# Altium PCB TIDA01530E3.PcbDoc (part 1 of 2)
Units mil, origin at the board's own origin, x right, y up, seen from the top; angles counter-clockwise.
Board outline 3700 x 4450 mil, 2 copper layers (Top Layer, Bottom Layer), stack 62 mil thick; 148 components, 116 nets, 531 pads, 208 vias.
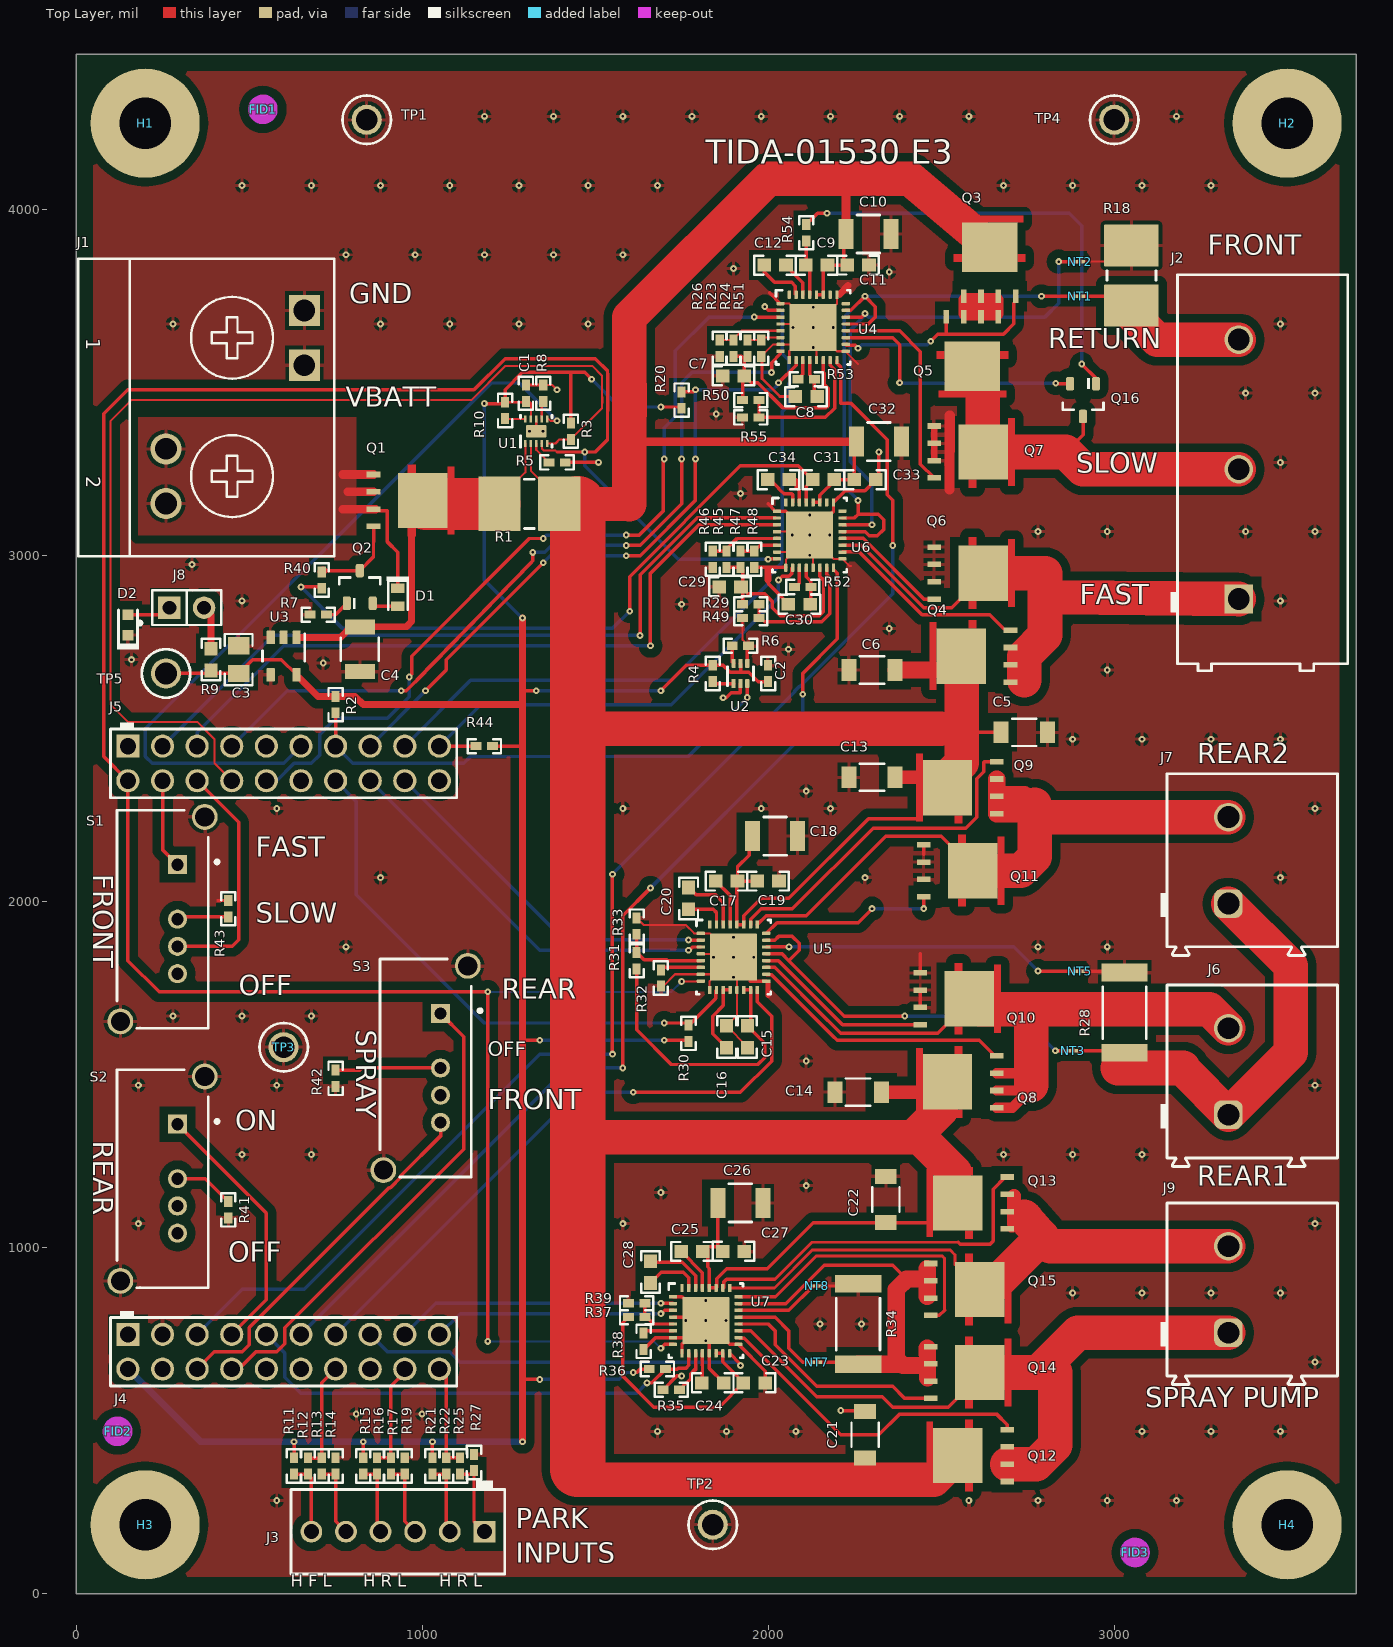
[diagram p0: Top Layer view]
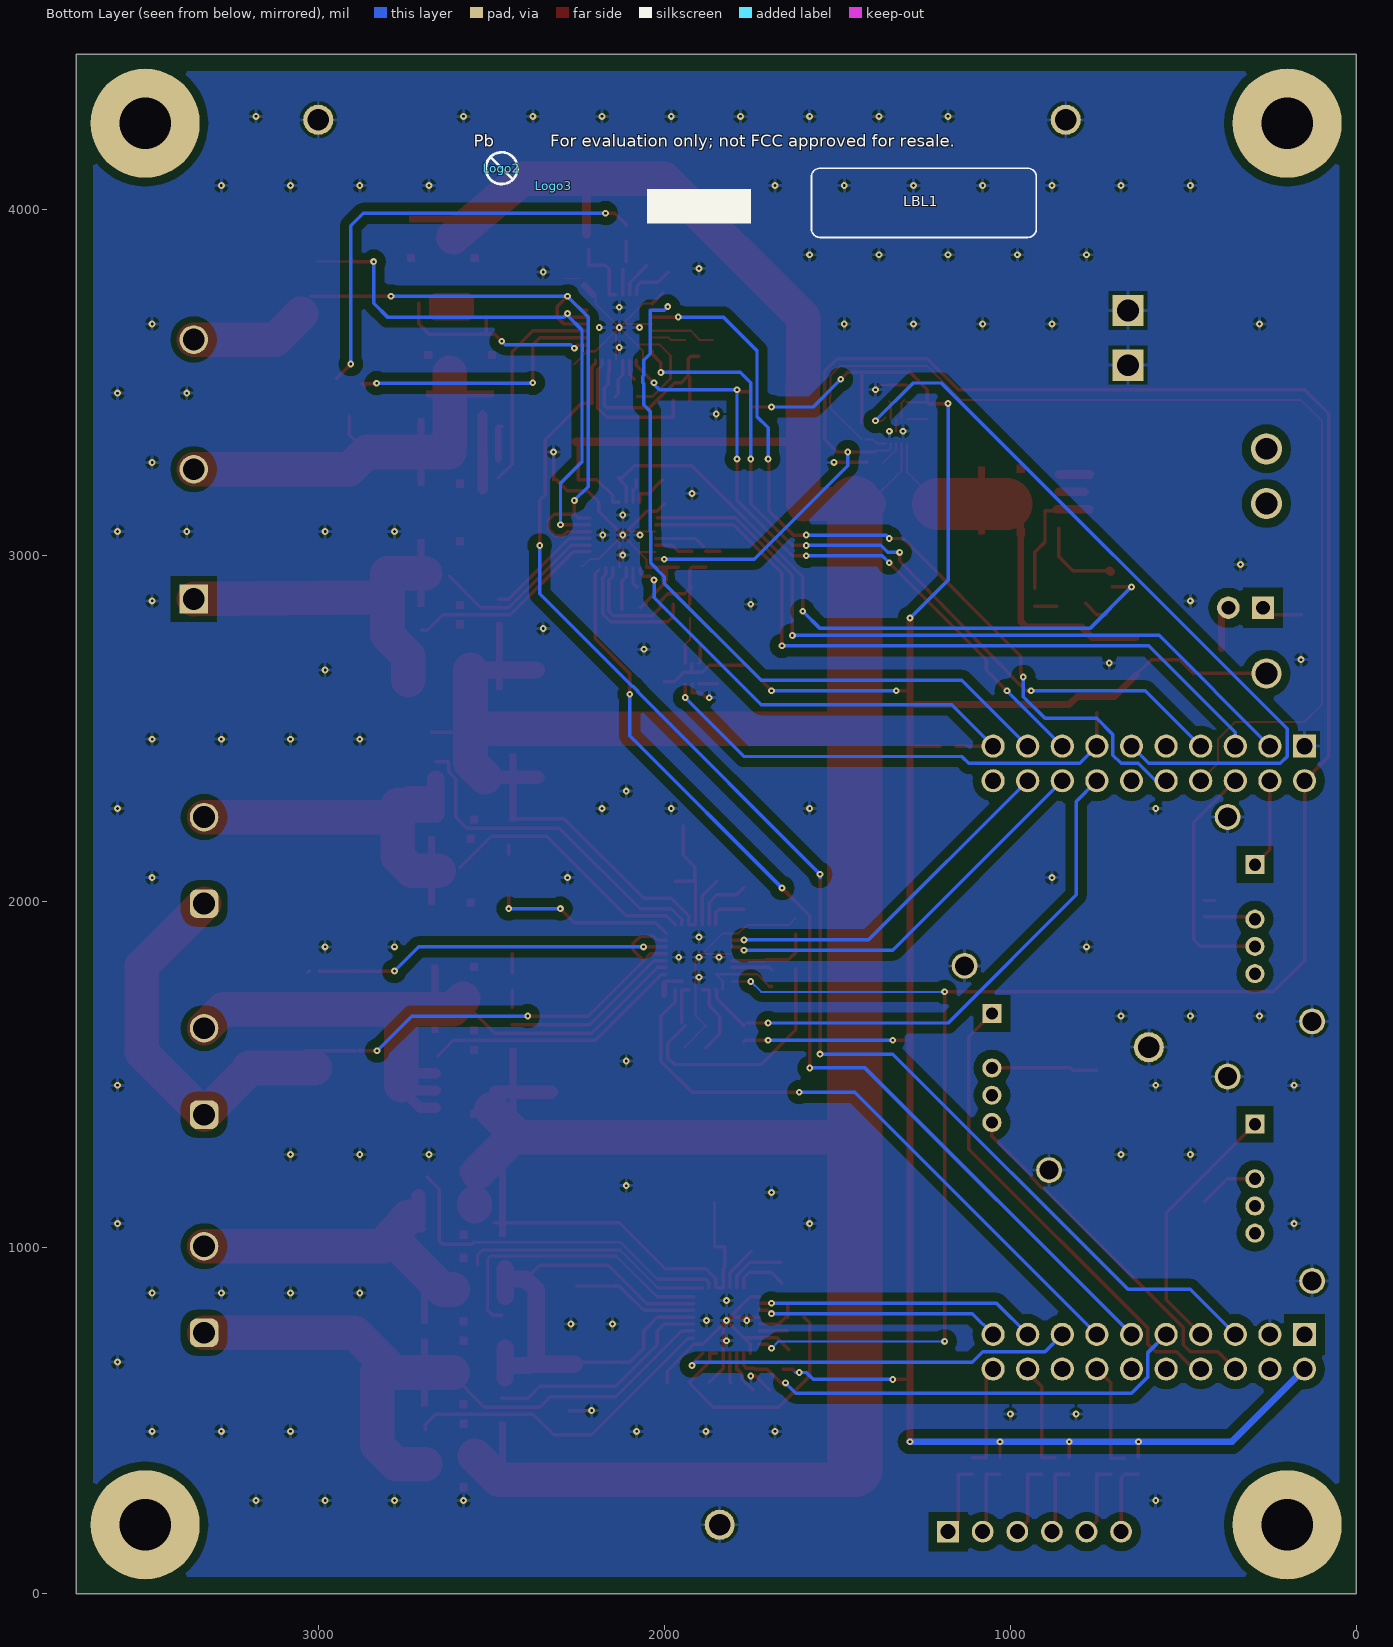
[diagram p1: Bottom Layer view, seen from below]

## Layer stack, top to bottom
Top Solder: solder mask 0.4, Solder Resist, Dk 3.5
Top Layer: signal copper 2.8
Dielectric1: core 56.4, FR-4, Dk 4.8
Bottom Layer: signal copper 2.8
Bottom Solder: solder mask 0.4, Solder Resist, Dk 3.5

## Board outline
0,0 0,4450 3700,4450 3700,0

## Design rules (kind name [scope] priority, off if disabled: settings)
AcuteAngle [All] p1: minimum=4.50000000000000E+0001 checktracksonly=FALSE
AssemblyTestPointUsage [All] p1: valid=2
BoardOutlineClearance BoardOutlineClearance_MountingHoles [OnCopper and InComponentClass('Mounting Holes')] p1: gap=40 ignorepadtopadclearanceinfootprint=FALSE
BoardOutlineClearance BoardOutlineClearance_Poly [OnCopper and IsPoly] p2: gap=25 ignorepadtopadclearanceinfootprint=FALSE
BoardOutlineClearance [OnCopper and Not InComponentClass('Logo') and not InComponentClass('FiducialMark') and not InRegion(1000,500,4000,800) and not InPoly] p3: gap=75 ignorepadtopadclearanceinfootprint=FALSE
Clearance Clearance_Keepouts [((IsTrack Or IsArc) And Not InPoly) And IsFree and IsKeepOut vs ((IsTrack Or IsArc) And Not InPoly) And IsFree and IsKeepOut] p1: gap=0 ignorepadtopadclearanceinfootprint=FALSE
Clearance Clearance_Poly [InPolygon] p2: gap=25 ignorepadtopadclearanceinfootprint=FALSE except(0: Arc-Hole Track-Hole SMDPad-Hole THPad-Hole Via-Hole Fill-Hole Poly-Hole Region-Hole Text-Hole)
Clearance [All] p3: gap=7.87 ignorepadtopadclearanceinfootprint=FALSE except(0: Arc-Hole Track-Hole SMDPad-Hole THPad-Hole Via-Hole Fill-Hole Poly-Hole Region-Hole Text-Hole)
ComponentClearance ComponentClearance_MountingHoles_FiducialMarks [InComponentClass('Mounting Holes') vs InComponentClass('FiducialMark')] p1: gap=50 collisioncheckmode=3 verticalgap=10 showdistances=FALSE
ComponentClearance ComponentClearance_Shunt [InComponentClass('Header') vs InComponentClass('Shunt')] p2: gap=0 collisioncheckmode=3 verticalgap=0 showdistances=FALSE
ComponentClearance ComponentClearance_Logo [InComponentClass('Logo')] p3: gap=50 collisioncheckmode=3 verticalgap=10 showdistances=FALSE
ComponentClearance ComponentClearance_ScrewToNut [(HasFootprint('NY PMS 440 0025 PH')) vs (HasFootprint('Keystone_1902C'))] p4: gap=5 collisioncheckmode=3 verticalgap=10 showdistances=FALSE
ComponentClearance ComponentClearance_MountingHoles [InComponentClass('Mounting Holes')] p5: gap=250 collisioncheckmode=3 verticalgap=100000 showdistances=FALSE
ComponentClearance ComponentClearance_SmallPassives [HasFootprint('0201*') or HasFootprint('0402*') or HasFootprint('0508') or HasFootprint('0603*') or HasFootprint('0612') or HasFootprint('0805*') or HasFootprint('0815*') or HasFootprint('0830*') or HasFootprint('1206*') or HasFootprint('1210*') or HasFootprint('1808*') or HasFootprint('1812*') or HasFootprint('1825*') or HasFootprint('2010*') or HasFootprint('2220*') or HasFootprint('2225*') or HasFootprint('2512*') or HasFootprint('2728*') or HasFootprint('3518*') vs HasFootprint('0201*') or HasFootprint('0402*') or HasFootprint('0508') or HasFootprint('0603*') or HasFootprint('0612') or HasFootprint('0805*') or HasFootprint('0815*') or HasFootprint('0830*') or HasFootprint('1206*') or HasFootprint('1210*') or HasFootprint('1808*') or HasFootprint('1812*') or HasFootprint('1825*') or HasFootprint('2010*') or HasFootprint('2220*') or HasFootprint('2225*') or HasFootprint('2512*') or HasFootprint('2728*') or HasFootprint('3518*')] p6: gap=14.96 collisioncheckmode=3 verticalgap=10 showdistances=FALSE
ComponentClearance ComponentClearance_THtoSMT [IsThruComponent vs IsSMTComponent] p7: gap=40 collisioncheckmode=3 verticalgap=30 showdistances=FALSE
ComponentClearance ComponentClearance_THtoTH [IsThruComponent vs IsThruComponent] p8: gap=30 collisioncheckmode=3 verticalgap=30 showdistances=FALSE
ComponentClearance [All] p9: gap=30 collisioncheckmode=3 verticalgap=10 showdistances=FALSE
DiffPairsRouting [All] p1: maxlimit=100 minlimit=10 mostfreqgap=10 toplayer_minwidth=15 toplayer_maxwidth=15 toplayer_prefwidth=15 bottomlayer_minwidth=15 bottomlayer_maxwidth=15 bottomlayer_prefwidth=15 maxuncoupledlength=1000
FabricationTestPointUsage TestPointUsage [All] p1: valid=2 allowmultiple=FALSE
FabricationTestpoint Testpoint [All] p1: side=3 testpointundercomponent=TRUE minsize=40 maxsize=100 preferedsize=60 minholesize=0 maxholesize=40 preferedholesize=32 testpointgrid=1 allowsidetop=TRUE allowsidebottom=TRUE usegrid=TRUE gridtolerance=0.01
FanoutControl Fanout_LCC [IsLCC] p1: bgadir=Out bgaviamode=Centered fanoutstyle=Auto fanoutdirection=Alternating viagrid=1 // Fanout_LCC (Default Rule)
FanoutControl Fanout_BGA [IsBGA] p2: bgadir=Out bgaviamode=Centered fanoutstyle=Auto fanoutdirection=Alternating viagrid=1 // Fanout_BGA (Default Rule)
FanoutControl Fanout_Default [All] p4: bgadir=Out bgaviamode=Centered fanoutstyle=Auto fanoutdirection=Alternating viagrid=1 // Fanout_Default (Default Rule)
FanoutControl Fanout_Small [(CompPinCount < 5)] p5: bgadir=Out bgaviamode=Centered fanoutstyle=Auto fanoutdirection=OutThenIn viagrid=1 // Fanout_Small (Default Rule)
HoleSize [All] p1: absolutevalues=TRUE maxlimit=251 minlimit=7.87 maxpercent=80.000 minpercent=20.000
MinimumAnnularRing MinimumAnnularRing_ThermalPadVias [IsVia and InAnyComponent] p1: minimumring=5.91
MinimumAnnularRing [All] p2: minimumring=5.9
MinimumSolderMaskSliver MinimumSolderMaskSliver_Logo [InComponentClass('Logo') vs InComponentClass('Logo')] p1: minsoldermaskwidth=0.7
MinimumSolderMaskSliver [All] p2: minsoldermaskwidth=3.94
PlaneConnect [All] p1: planeconnectstyle=Relief reliefexpansion=10 reliefentries=4 reliefconductorwidth=10 reliefairgap=10
PolygonConnect [All] p1: connectstyle=Relief reliefconductorwidth=10 reliefentries=4 polygonreliefangle="90 Angle" airgapwidth=10
RoutingVias ThermalPadVias [IsVia and InAnyComponent] p1: holewidth=7.87 width=19.68 viastyle="Through Hole" minholewidth=7.87 minwidth=19.68 maxholewidth=12.99 maxwidth=23.62
RoutingVias [All] p2: holewidth=16 width=34 viastyle="Through Hole" minholewidth=7 minwidth=19 maxholewidth=40 maxwidth=65
SilkToBoardRegionClearance [Not ((IsComment or IsDesignator) And (Hide <> 'False')) and not InRegion(1000,500,4000,800)] p1:
SilkToSilkClearance SilkToSilkClearance_Pb-FreeLogo [(HasFootprint('Pb-Free_Overlay_Medium') OR HasFootprint('Pb-Free_Overlay_Small')) vs (HasFootprint('Pb-Free_Overlay_Medium') OR HasFootprint('Pb-Free_Overlay_Small'))] p1: silktosilkclearance=0
SilkToSilkClearance [All] p2: silktosilkclearance=4
SilkToSolderMaskClearance SilkToComponentPadClearance [(IsPad or IsFill or IsRegion) and InAnycomponent] p1: minsilkscreentomaskgap=4 clearancetoexposedcopper=TRUE
SilkToSolderMaskClearance "Silk to Solder Mask Opening" [All] p2: minsilkscreentomaskgap=4 clearancetoexposedcopper=FALSE
SolderMaskExpansion [All] p1: expansion=1.97
Width [All] p1: maxlimit=160 minlimit=6 preferedwidth=10 minimp=50.000000 maximp=50.000000 favimp=50.000000 checkconnectedcopper=TRUE
15 further rules are at their usual default settings.

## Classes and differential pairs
component class "TIDA01530 Front Wipers 2x 8702D v2": C1 C2 C3 C4 C5 C6 C7 C8 C9 C10 C11 C12 C29 C30 C31 C32 C33 C34 D1 D2 D? J1 J2 J4 J5 J8 NT1 NT2 Q1 Q2 Q3 Q4 Q5 Q6 Q7 Q16 R1 R2 R3 R4 R5 R6 R7 R8 R9 R10 R18 R20 R23 R24 R26 R29 R40 R44 R45 R46 R47 R48 R49 R50 R51 R52 R53 R54 R55 U1 U2 U3 U4 U6
component class "TIDA01530 Rear Wipers": C13 C14 C15 C16 C17 C18 C19 C20 C21 C22 C23 C24 C25 C26 C27 C28 C? J6 J7 J9 NT3 NT5 NT7 NT8 NT? Q8 Q9 Q10 Q11 Q12 Q13 Q14 Q15 Q? R28 R30 R31 R32 R33 R34 R35 R36 R37 R38 R39 R? U5 U7 U?
component class "Mounting Holes": H1 H2 H3 H4
component class "TIDA01530 Switches Connectors": FID1 FID2 FID3 H1 H2 H3 H4 J3 LBL1 Logo2 Logo3 R11 R12 R13 R14 R15 R16 R17 R19 R21 R22 R25 R27 R41 R42 R43 S1 S2 S3 S? TP1 TP2 TP3 TP4 TP5 TP? ZZ1
component class FiducialMark: FID1 FID2 FID3
component class AssemblyNote: ZZ1
component class Label: LBL1
component class Header: J8

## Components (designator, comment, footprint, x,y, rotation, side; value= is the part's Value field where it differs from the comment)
C1 "C0402C104K4RACAUTO" 0402 1300,3470 r90 top value=0.1uF
C2 "C0402C104K4RACAUTO" 0402 2000,2660 r90 top value=0.1uF
C3 "C2012X7R1A475M125AC" 0805_HV 470,2700 r90 top value=4.7uF
C4 "UMK325AB7106KMHT" 1210_280 820,2730 r270 top value=10uF
C5 "CL31B106KBHNNNE" 1206_180 2740,2490 r0 top value=10uF
C6 "CL31B106KBHNNNE" 1206_180 2300,2670 r180 top value=10uF
C7 "GRM188R70J105KA01D" 0603 1900,3520 r180 top value=1uF
C8 "GRM188R70J105KA01D" 0603 2110,3460 r180 top value=1uF
C9 "C1608X7R1C105K080AC" 0603 2140,3840 r180 top value=1uF
C10 "C3225X7S1H106K250AB" 1210_280 2290,3930 r0 top value=10uF
C11 "C1608X7R1H104K080AA" 0603 2260,3840 r0 top value=0.1uF
C12 "C1608X7R1H104K080AA" 0603 2020,3840 r180 top value=0.1uF
C13 "CL31B106KBHNNNE" 1206_180 2300,2360 r180 top value=10uF
C14 "CL31B106KBHNNNE" 1206_180 2260,1450 r180 top value=10uF
C15 "GRM188R70J105KA01D" 0603 1940,1610 r270 top value=1uF
C16 "GRM188R70J105KA01D" 0603 1880,1610 r90 top value=1uF
C17 "C1608X7R1C105K080AC" 0603 1880,2060 r180 top value=1uF
C18 "C3225X7S1H106K250AB" 1210_280 2020,2190 r0 top value=10uF
C19 "C1608X7R1H104K080AA" 0603 2000,2060 r0 top value=0.1uF
C20 "C1608X7R1H104K080AA" 0603 1770,2010 r270 top value=0.1uF
C21 "CL31B106KBHNNNE" 1206_180 2280,460 r90 top value=10uF
C22 "CL31B106KBHNNNE" 1206_180 2340,1140 r90 top value=10uF
C23 "GRM188R70J105KA01D" 0603 1960,610 r0 top value=1uF
C24 "GRM188R70J105KA01D" 0603 1840,610 r0 top value=1uF
C25 "C1608X7R1C105K080AC" 0603 1780,990 r180 top value=1uF
C26 "C3225X7S1H106K250AB" 1210_280 1920,1130 r0 top value=10uF
C27 "C1608X7R1H104K080AA" 0603 1900,990 r0 top value=0.1uF
C28 "C1608X7R1H104K080AA" 0603 1660,930 r270 top value=0.1uF
C29 "GRM188R70J105KA01D" 0603 1890,2910 r180 top value=1uF
C30 "GRM188R70J105KA01D" 0603 2090,2860 r180 top value=1uF
C31 "C1608X7R1C105K080AC" 0603 2160,3220 r180 top value=1uF
C32 "C3225X7S1H106K250AB" 1210_280 2320,3330 r0 top value=10uF
C33 "C1608X7R1H104K080AA" 0603 2280,3220 r0 top value=0.1uF
C34 "C1608X7R1H104K080AA" 0603 2030,3220 r180 top value=0.1uF
D1 "CD0603-S0180" Diode_0603 930,2880 r270 top value=90V
D2 "LTST-C191KFKT" LTST-C191_Orange 150,2800 r270 top value=Orange
FID1 "Fiducial" Fiducial10-20 540,4290 r0 top
FID2 "Fiducial" Fiducial10-20 120,470 r0 top
FID3 "Fiducial" Fiducial10-20 3060,120 r0 top
H1 "NY PMS 440 0025 PH" "NY PMS 440 0025 PH" 200,4250 r0 top locked
H2 "NY PMS 440 0025 PH" "NY PMS 440 0025 PH" 3500,4250 r0 top
H3 "NY PMS 440 0025 PH" "NY PMS 440 0025 PH" 200,200 r0 top locked
H4 "NY PMS 440 0025 PH" "NY PMS 440 0025 PH" 3500,200 r0 top
J1 "0399100102" CONN_399100102 460,3430 r270 top
J2 "OSTT7032150" On-Shore_OSTT7032150 3360,3250 r90 top
J3 "1725698" Phoenix_1725698 930,180 r180 top
J4 "CRD-081413-A-G" Major_CRD-081413-A-x 600,700 r90 top
J5 "CRD-081413-A-G" Major_CRD-081413-A-x 600,2400 r90 top
J6 "OSTT7020150" On-Shore_OSTT7020150 3330,1510 r90 top
J7 "OSTT7020150" On-Shore_OSTT7020150 3330,2120 r90 top
J8 "90120-0122" CONN_90120-0122 320,2850 r0 top
J9 "OSTT7020150" On-Shore_OSTT7020150 3330,880 r90 top
LBL1 "Size: 0.65\" x 0.20 \"" Label_650x200 1250,4020 r180 bottom
Logo2 "Pb-Free Symbol" Pb-Free_Overlay_Small 2470,4120 r180 bottom
Logo3 "FCC disclaimer" FCC_disclaimer 2320,4070 r180 bottom
NT1 "Net-Tie" Net-Tie_10mil 2900,3750 r0 top net-tie
NT2 "Net-Tie" Net-Tie_10mil 2900,3850 r0 top net-tie
NT3 "Net-Tie" Net-Tie_10mil 2880,1570 r0 top net-tie
NT5 "Net-Tie" Net-Tie_10mil 2900,1800 r0 top net-tie
NT7 "Net-Tie" Net-Tie_10mil 2140,670 r0 top net-tie
NT8 "Net-Tie" Net-Tie_10mil 2140,890 r0 top net-tie
Q1 "SQJA04EP-T1_GE3" PowerPAK_SO-8L 970,3160 r0 top value=60V
Q2 "MMBTA05LT1G" SOT-23 820,2910 r90 top value="60 V"
Q3 "SQJA06EP-T1_GE3" PowerPAK_SO-8L 2640,3860 r90 top value=60V
Q4 "SQJA06EP-T1_GE3" PowerPAK_SO-8L 2590,2710 r180 top value=60V
Q5 "SQJA06EP-T1_GE3" PowerPAK_SO-8L 2590,3580 r270 top value=60V
Q6 "SQJA06EP-T1_GE3" PowerPAK_SO-8L 2590,2950 r0 top value=60V
Q7 "SQJA06EP-T1_GE3" PowerPAK_SO-8L 2590,3300 r0 top value=60V
Q8 "SQJA06EP-T1_GE3" PowerPAK_SO-8L 2550,1480 r180 top value=60V
Q9 "SQJA06EP-T1_GE3" PowerPAK_SO-8L 2550,2330 r180 top value=60V
Q10 "SQJA06EP-T1_GE3" PowerPAK_SO-8L 2550,1720 r0 top value=60V
Q11 "SQJA06EP-T1_GE3" PowerPAK_SO-8L 2560,2090 r0 top value=60V
Q12 "SQJA06EP-T1_GE3" PowerPAK_SO-8L 2580,400 r180 top value=60V
Q13 "SQJA06EP-T1_GE3" PowerPAK_SO-8L 2580,1130 r180 top value=60V
Q14 "SQJA06EP-T1_GE3" PowerPAK_SO-8L 2580,640 r0 top value=60V
Q15 "SQJA06EP-T1_GE3" PowerPAK_SO-8L 2580,880 r0 top value=60V
Q16 "DMN62D0U-7" SOT-23 2910,3450 r270 top value=60V
R1 "CRE2512-FZ-R001E-3" CRE2512-R1_R4 1310,3150 r0 top value=0.001
R2 "CRCW040210K0JNED" 0402 750,2570 r90 top value=10k
R3 "CRCW040210K0JNED" 0402 1430,3360 r90 top value=10k
R4 "ERJ-2GE0R00X" 0402 1840,2660 r270 top value=0
R5 "CRCW04022K55FKED" 0402 1390,3270 r0 top value=2.55k
R6 "ERJ-2GE0R00X" 0402 1920,2740 r180 top value=0
R7 "CRCW040243K0JNED" 0402 700,2830 r0 top value=43k
R8 "ERJ-2GE0R00X" 0402 1350,3470 r90 top value=0
R9 "CRCW0603200RJNEA" 0603 390,2700 r90 top value=200
R10 "ERJ-2GE0R00X" 0402 1240,3420 r270 top value=0
R11 "CRCW0402100KJNED" 0402 630,370 r270 top value=100k
R12 "ERJ-2GE0R00X" 0402 670,370 r90 top value=0
R13 "ERJ-2GE0R00X" 0402 710,370 r90 top value=0
R14 "ERJ-2GE0R00X" 0402 750,370 r270 top value=0
R15 "CRCW0402100KJNED" 0402 830,370 r270 top value=100k
R16 "ERJ-2GE0R00X" 0402 870,370 r90 top value=0
R17 "ERJ-2GE0R00X" 0402 910,370 r90 top value=0
R18 "CRE2512-FZ-R003E-3" CRE2512-R1_R4 3050,3810 r270 top value=0.003
R19 "ERJ-2GE0R00X" 0402 950,370 r270 top value=0
R20 "CRCW040210K0JNED" 0402 1750,3450 r90 top value=10k
R21 "CRCW0402100KJNED" 0402 1030,370 r270 top value=100k
R22 "ERJ-2GE0R00X" 0402 1070,370 r90 top value=0
R23 "CRCW040268K0JNED" 0402 1900,3600 r270 top value=68k
R24 "CRCW0402200KJNED" 0402 1940,3600 r90 top value=200k
R25 "ERJ-2GE0R00X" 0402 1110,370 r90 top value=0
R26 "CRCW0402200KJNED" 0402 1860,3600 r270 top value=200k
R27 "ERJ-2GE0R00X" 0402 1150,380 r270 top value=0
R28 "MCS3264R005FER" 2512 3030,1680 r270 top value=0.005
R29 "CRCW040268K0JNED" 0402 1950,2860 r0 top value=68k
R30 "CRCW040210K0JNED" 0402 1770,1620 r90 top value=10k
R31 "CRCW040268K0JNED" 0402 1620,1830 r90 top value=68k
R32 "CRCW0402200KJNED" 0402 1690,1780 r270 top value=200k
R33 "CRCW0402200KJNED" 0402 1620,1930 r90 top value=200k
R34 "MCS3264R005FER" 2512 2260,780 r270 top value=0.005
R35 "ERJ-2GE0R00X" 0402 1720,590 r0 top value=0
R36 "CRCW040210K0JNED" 0402 1680,650 r0 top value=10k
R37 "CRCW040268K0JNED" 0402 1620,800 r180 top value=68k
R38 "CRCW0402200KJNED" 0402 1640,730 r270 top value=200k
R39 "CRCW0402200KJNED" 0402 1620,840 r180 top value=200k
R40 "CRCW040210K0JNED" 0402 710,2930 r270 top value=10k
R41 "ERJ-2GE0R00X" 0402 440,1110 r90 top value=0
R42 "ERJ-2GE0R00X" 0402 750,1490 r90 top value=0
R43 "ERJ-2GE0R00X" 0402 440,1980 r270 top value=0
R44 "CRCW040210K0JNED" 0402 1180,2450 r180 top value=10k
R45 "CRCW040268K0JNED" 0402 1880,2990 r270 top value=68k
R46 "CRCW0402200KJNED" 0402 1840,2990 r270 top value=200k
R47 "CRCW0402200KJNED" 0402 1920,2990 r90 top value=200k
R48 "CRCW0402200KJNED" 0402 1960,2990 r90 top value=200k
R49 "CRCW040211K0JNED" 0402 1950,2820 r180 top value=11k
R50 "CRCW040268K0JNED" 0402 1950,3450 r0 top value=68k
R51 "CRCW0402200KJNED" 0402 1980,3600 r90 top value=200k
R52 "ERJ-2GE0R00X" 0402 2100,2910 r180 top value=0
R53 "ERJ-2GE0R00X" 0402 2110,3510 r180 top value=0
R54 "CRCW040210K0JNED" 0402 2110,3933.62 r270 top value=10k
R55 "CRCW040211K0JNED" 0402 1950,3400 r180 top value=11k
S1 "1825255-7" SW_1825255-8 250,1950 r270 top
S2 "1825255-7" SW_1825255-8 250,1200 r270 top
S3 "1825255-7" SW_1825255-8 1010,1520 r270 top
TP1 "5011" Keystone5011 840,4260 r90 top
TP2 "5011" Keystone5011 1840,200 r90 top
TP3 "5011" Keystone5011 600,1580 r90 top
TP4 "5011" Keystone5011 3000,4260 r90 top
TP5 "5008" Keystone5008 260,2660 r90 top
U1 "INA300AIDSQR" DSQ0010A 1330,3360 r90 top
U2 "TMP302DQDRLRQ1" DRL0006A 1920,2660 r90 top
U3 "TPS7B6933QDBVRQ1" DBV0005A_N 600,2710 r270 top
U4 "DRV8702DQRHBRQ1" RHB0032E 2130,3660 r0 top
U5 "DRV8702QRHBRQ1" RHB0032E 1900,1840 r0 top
U6 "DRV8702DQRHBRQ1" RHB0032E 2120,3060 r0 top
U7 "DRV8702QRHBRQ1" RHB0032E 1820,790 r0 top
ZZ1 "This Assembly Note is for PCB labels only" AssemblyNoteLabel 660,4790 r0 top

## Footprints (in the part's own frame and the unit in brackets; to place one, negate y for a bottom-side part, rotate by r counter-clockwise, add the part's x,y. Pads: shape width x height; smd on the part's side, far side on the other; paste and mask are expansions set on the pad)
0402 [mm] "0402 from SM-752 data"
  rect 0.8x0.6 smd: 1(-0.6,0) 2(0.6,0)
  silkscreen extent -1.22,-0.52 1.22,0.52, body extent -0.55,-0.3 0.55,0.3, height 0.6
0603 [mm] "0603 from SM-752 data"
  rect 1x0.95 smd: 1(-0.8,0) 2(0.8,0)
  silkscreen extent -1.52,-0.69 1.52,0.69, body extent -0.87,-0.47 0.87,0.47, height 1
0805_HV [mil] "0805 with 30mil clearance between pads"
  rect 50x63 smd: 1(-40,0) 2(40,0)
  silkscreen extent -74,-40 74,40, body extent -43,-29 43,29, height 57
1206_180 [mm] "1206_180"
  rect 1.1x1.6 smd: 1(-1.7,0) 2(1.7,0)
  silkscreen extent -0.9,-1 0.9,1, body extent -1.75,-0.95 1.75,0.95, height 1.8
1210_280 [mm] "SMD, 2-Leads, Body 3.6x2.8mm, Height 2.8mm"
  rect 1.1x2.2 smd: 1(-1.65,0) 2(1.65,0)
  silkscreen extent -0.84,-1.4 0.84,1.4, body extent -1.8,-1.4 1.8,1.4, height 2.8
2512 [mm] "Chip Resistor, Body 6.3x3.2mm, IPC Medium Density"
  rect 1.3x3.4 smd: 1(-2.95,0) 2(2.95,0)
  silkscreen extent -1.9,-1.6 1.9,1.6, body extent -3.22,-1.67 3.22,1.67, height 0.71
AssemblyNoteLabel [mil] "Assembly Note for PCB Labels"
CONN_90120-0122 [mm] "Molex"
  rect 1.65x1.65 hole 1.016 mask+0: 1(-1.27,0)
  round 1.65 hole 1.016 mask+0: 2(1.27,0)
  silkscreen extent -3.56,-1.27 2.54,1.27, body extent -2.54,-1.27 2.54,1.27, height 9.29
CONN_399100102 [mm] "Molex"
  rect 2.3x2.3 hole 1.587: 1(-7.085,5.08) 1A(-3.075,5.08)
  round 2.3 hole 1.587: 2(3.075,-5.08) 2A(7.085,-5.08)
  silkscreen extent -10.88,-11.53 10.96,7.27, body extent -10.88,-11.53 10.96,7.27, height 31.1
CRE2512-R1_R4 [mm] "SMD, 2-Leads, Body 6.45x3.35mm"
  rrect3% 3.1x4 smd: 1(-2.2,0) 2(2.2,0)
  silkscreen extent -0.35,-1.8 0.35,1.8, body extent -3.32,-1.77 3.33,1.78, height 0.9
DBV0005A_N [mm] "SOT23, 5-Leads, Body 2.9x1.6mm, Pitch 0.95mm, Lead Span 2.8mm, IPC Medium Density"
  rrect17% 1x0.6 smd: 1(-1.375,0.95) 2(-1.375,0) 3(-1.375,-0.95) 4(1.375,-0.95) 5(1.375,0.95)
  silkscreen extent -1.62,-1.55 0.38,1.55, body extent -1.42,-1.46 1.42,1.46, height 1.09
Diode_0603 [mm] "Based on Bourns recommended land pattern Rev 10/09"
  rect 0.7x1 smd: 1(-0.65,0) 2(0.65,0)
  silkscreen extent -1.5,-0.8 0.9,0.8, body extent -0.9,-0.5 0.9,0.5, height 0.85
DRL0006A [mm] "SOTFL, 6-Flat Leads, Body 1.2x1.6x0.6mm, Pitch 0.5mm, TI recommended"
  rrect33% 0.67x0.3 smd: 1(-0.74,0.5) 2(-0.74,0) 3(-0.74,-0.5) 4(0.74,-0.5) 5(0.74,0) 6(0.74,0.5)
  silkscreen extent -0.9,-0.95 0.5,0.95, body extent -0.8,-0.8 0.8,0.8, height 0.61
DSQ0010A [mm] "SON, 10-Leads, Body 2x2mm, Pitch 0.4mm, Thermal Pad 1.5x0.9mm, TI Recommended"
  rrect50% 0.5x0.2 smd: 1(-0.9,0.8) 2(-0.9,0.4) 3(-0.9,0) 4(-0.9,-0.4) 5(-0.9,-0.8) 6(0.9,-0.8) 7(0.9,-0.4) 8(0.9,0) 9(0.9,0.4) 10(0.9,0.8)
  rrect11% 0.9x1.5 smd paste-0.45: 11(0,0)
  silkscreen extent -1.18,-1.15 1.18,1.15, body extent -1.05,-1.05 1.05,1.05, height 0.81
FCC_disclaimer [mil]
Fiducial10-20 [mm]
  round 1 smd mask+0.5: 1(0,0)
  Top Layer keep-out circle w1.178: c0,0 r0.5
Keystone5008 [mil] "Keystone Compact loops"
  round 87 hole 63: 1(0,0)
  silkscreen extent -70,-70 70,70, body extent -63,-63 62,63, height 225
Keystone5011 [mil] "Keystone Multipurpose loops"
  round 87 hole 63: 1(0,0)
  silkscreen extent -70,-70 70,70, body extent -63,-63 63,62, height 319
Label_650x200 [mil] "Thermal Transfer Label"
  silkscreen extent -325,-100 325,100, body extent -325,-100 325,100, height 1
LTST-C191_Orange [mm] "SMD, 2-Leads, Body 1.6x0.8mm"
  rect 0.8x0.8 smd: 1(-0.75,0) 2(0.75,0)
  silkscreen extent -1.1,-0.8 1.8,0.8, body extent -0.85,-0.45 0.85,0.45, height 0.65
Major_CRD-081413-A-x [mm] "Receptacle, 2.54 mm, 10x2, TH"
  rect 1.7x1.7 hole 1.2: 1(1.27,11.43)
  round 1.7 hole 1.2: 2(-1.27,11.43) 3(1.27,8.89) 4(-1.27,8.89) 5(1.27,6.35) 6(-1.27,6.35) 7(1.27,3.81) 8(-1.27,3.81) 9(1.27,1.27) 10(-1.27,1.27) 11(1.27,-1.27) 12(-1.27,-1.27) 13(1.27,-3.81) 14(-1.27,-3.81) 15(1.27,-6.35) 16(-1.27,-6.35) 17(1.27,-8.89) 18(-1.27,-8.89) 19(1.27,-11.43) 20(-1.27,-11.43)
  silkscreen extent -2.52,-12.7 3,12.7, body extent -2.52,-12.71 2.52,12.71, height 8.64
Net-Tie_10mil [mil] "10mil net tie, no solder mask opening, no solder paste"
  rect 10x10 smd paste-5 mask-5: 1(-10,0) 2(10,0)
  Top Layer region: -6,5 6,5 6,-5 -6,-5
"NY PMS 440 0025 PH" [mm] "4-40 nylon screw and mounting hole"
  round 8 hole 3.81: 1(0,0)
  body extent -3.3,-3.3 3.3,3.3, height 2.69
On-Shore_OSTT7020150 [mm] "Terminal Block, 6.35mm, 2x1, TH"
  rrect50% 2.1x2.1 hole 1.6: 1(-3.175,0)
  round 2.1 hole 1.6: 2(3.175,0)
  silkscreen extent -6.98,-8 6.35,5, body extent -6.98,-8 6.35,4.5, height 21.5
On-Shore_OSTT7032150 [mm] "Terminal Block, 3x1, 9.52mm, TH"
  rect 2.1x2.1 hole 1.6: 1(-9.52,0)
  round 2.1 hole 1.6: 2(0,0) 3(9.52,0)
  silkscreen extent -14.78,-8 14.28,5, body extent -14.78,-8 14.28,4.5, height 21.5
Pb-Free_Overlay_Small [mil]
  silkscreen extent -46,-46 46,46
Phoenix_1725698 [mm] "Terminal Block, 6x1, 2.54mm, TH"
  rect 1.6x1.6 hole 1.1: 1(-6.35,0)
  round 1.6 hole 1.1: 2(-3.81,0) 3(-1.27,0) 4(1.27,0) 5(3.81,0) 6(6.35,0)
  silkscreen extent -7.85,-3.75 7.85,3.1, body extent -7.85,-3.1 7.85,3.1, height 8.51
PowerPAK_SO-8L [mm] "based on Vishay recommended land pattern Document 63818 Feb 7, 2012"
  rect 1x0.41 smd: 1(-2.805,1.905) 2(-2.805,0.635) 3(-2.805,-0.635) 4(-2.805,-1.905)
  rect 3.63x4.061 smd: 5(0.805,0)
  Top Layer region: -0.297,-2.64 0.297,-2.64 0.297,-2.03 -0.297,-2.03
  Top Layer region: -0.297,2.03 0.297,2.03 0.297,2.64 -0.297,2.64
  Top Layer region: 2.615,-2.5 3.125,-2.5 3.125,2.5 2.615,2.5
  body extent -3.07,-2.57 3.08,2.57, height 1.21
RHB0032E [mm] "QFN, 32-Leads, Body 5x5mm, Pitch 0.5mm, Thermal Pad 3.45x3.45mm, TI Recommended"
  rrect40% 0.6x0.25 smd: 1(-2.4,1.75) 2(-2.4,1.25) 3(-2.4,0.75) 4(-2.4,0.25) 5(-2.4,-0.25) 6(-2.4,-0.75) 7(-2.4,-1.25) 8(-2.4,-1.75) 17(2.4,-1.75) 18(2.4,-1.25) 19(2.4,-0.75) 20(2.4,-0.25) 21(2.4,0.25) 22(2.4,0.75) 23(2.4,1.25) 24(2.4,1.75)
  rrect40% 0.25x0.6 smd: 9(-1.75,-2.4) 10(-1.25,-2.4) 11(-0.75,-2.4) 12(-0.25,-2.4) 13(0.25,-2.4) 14(0.75,-2.4) 15(1.25,-2.4) 16(1.75,-2.4) 25(1.75,2.4) 26(1.25,2.4) 27(0.75,2.4) 28(0.25,2.4) 29(-0.25,2.4) 30(-0.75,2.4) 31(-1.25,2.4) 32(-1.75,2.4)
  rrect3% 3.45x3.45 smd paste-1.725: 33(0,0)
  rrect7% 1.49x1.49 on Top Paste: ""(-0.845,-0.845) ""(-0.845,0.845) ""(0.845,-0.845) ""(0.845,0.845)
  silkscreen extent -2.72,-2.73 2.72,2.73, body extent -2.57,-2.57 2.58,2.58, height 1.01
SOT-23 [mm] "SOT23, 3-Leads, Body 2.9x1.3mm, Pitch 0.95mm, Lead Span 2.5mm, IPC Medium Density"
  rrect50% 1x0.6 smd: 1(-1.2,0.95) 2(-1.2,-0.95) 3(1.2,0)
  silkscreen extent -1.63,-1.5 0.7,1.5, body extent -1.16,-1.45 1.21,1.45, height 1
SW_1825255-8 [mm] "Switch, 4-Leads, SP3T, Body 16x6.7mm, TH"
  rect 1.4x1.4 / inner round 1.4 / far side rect 1.4x1.4 hole 0.9: 1(-4,1.1)
  round 1.4 hole 0.9: 2(0,1.1) 3(2,1.1) 4(4,1.1)
  round 1.9 hole 1.4: G1(7.5,-3.1) G2(-7.5,3.1)
  silkscreen extent -8,-3.35 8,4.13, body extent -8,-3.35 8,3.35, height 17.5

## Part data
C1 C2: "CAP, CERM, 0.1 µF, 16 V,+/- 10%, X7R, AEC-Q200 Grade 1, 0402", Cap_Case=0402, Manufacturer=Kemet, Supplier Part Number 1=399-6828-1-ND, TempCo=X7R, Tolerance_%=10, Value2=16V, ValueDisplayed=0.1µF
C3: "CAP, CERM, 4.7 µF, 10 V,+/- 20%, X7R, 0805", Cap_Case=0805, Manufacturer=TDK, Supplier Part Number 1=445-1605-1-ND, TempCo=X7R, Tolerance_%=20, Value2=10V, ValueDisplayed=4.7µF
C4: "CAP, CERM, 10 µF, 50 V,+/- 10%, X7R, AEC-Q200 Grade 1, 1210", Cap_Case=1210, Manufacturer="Taiyo Yuden", Supplier Part Number 1=587-4326-1-ND, TempCo=X7R, Tolerance_%=10, Value2=50V, ValueDisplayed=10µF
C5 C6 C13 C14 C21 C22: "CAP, CERM, 10 µF, 50 V,+/- 10%, X7R, 1206", Cap_Case=1206, Manufacturer="Samsung Electro-Mechanics", Supplier Part Number 1=1276-6767-1-ND, TempCo=X7R, Tolerance_%=10, Value2=50V, ValueDisplayed=10µF
C7 C8 C15 C16 C23 C24 C29 C30: "CAP, CERM, 1 µF, 6.3 V,+/- 10%, X7R, 0603", Cap_Case=0603, Manufacturer=MuRata, Supplier Part Number 1=490-3898-1-ND, TempCo=X7R, Tolerance_%=10, Value2=6.3V, ValueDisplayed=1µF
C9 C17 C25 C31: "CAP, CERM, 1 µF, 16 V,+/- 10%, X7R, 0603", Cap_Case=0603, Manufacturer=TDK, Supplier Part Number 1=445-1604-1-ND, TempCo=X7R, Tolerance_%=10, Value1="0.0057 ohm", Value2=16V, ValueDisplayed=1µF
C10 C18 C26 C32: "CAP, CERM, 10 µF, 50 V,+/- 10%, X7S, 1210", Cap_Case=1210, Manufacturer=TDK, Supplier Part Number 1=445-4536-1-ND, TempCo=X7S, Tolerance_%=10, Value1="0.002827 ohm", Value2=50V, ValueDisplayed=10µF
C11 C12 C19 C20 C27 C28 C33 C34: "CAP, CERM, 0.1 µF, 50 V,+/- 10%, X7R, 0603", Cap_Case=0603, Manufacturer=TDK, Supplier Part Number 1=445-1314-1-ND, TempCo=X7R, Tolerance_%=10, Value1="0.0296 ohm", Value2=50V, ValueDisplayed=0.1µF
D1: library part CMP-0029009-1, "Diode, Switching, 90 V, 0.1 A, 0603 Diode", Manufacturer=Bourns, Supplier Part Number 1=652-CD0603-S0180, Value1=0.1A, Value2=1V
D2: "LED, Orange, SMD", Color=Orange, Manufacturer=Lite-On, Power_TotalModule=0.075, Supplier Part Number 1=160-1445-1-ND, Value1=0.075W, Value2=2V
FID1 FID2 FID3: "Fiducial mark.  There is nothing to buy or mount.", Manufacturer=N/A
H1 H2 H3 H4: "Machine Screw, Round, #4-40 x 1/4, Nylon, Philips panhead", DigiKeyPartNumber=H542-ND, Manufacturer="B&F Fastener Supply"
J1: "Terminal Block, 60A, 10.16mm Pitch, 2-Pos, TH", Manufacturer=Molex, Supplier Part Number 1=WM5964-ND
J2: "Terminal Block, 3x1, 9.52mm, TH", Color=Green, Manufacturer="On-Shore Technology", Supplier Part Number 1=ED2678-ND
J3: library part CMP-0055512-1, "Terminal Block, 6x1, 2.54mm, TH", Color=Green, Current_A=6A, Manufacturer="Phoenix Contact", Supplier Part Number 1=277-1277-ND, Voltage_V=160V
J4 J5: "Receptacle, 2.54 mm, 10x2, Gold, TH", Manufacturer="Major League Electronics"
J6 J7 J9: "Terminal Block, 6.35mm, 2x1, TH", Color=Green, Current_A=30, Manufacturer="On-Shore Technology", Supplier Part Number 1=ED2675-ND, Voltage_V=300
J8: "Header, 100mil, 2x1, Tin, TH", Manufacturer=Molex, Supplier Part Number 1=WM8072-ND
LBL1: library part THT-14-423-10, "Thermal Transfer Printable Labels, 0.650\" W x 0.200\" H - 10,000 per roll", Alternate Manufacturer=-, Manufacturer=Brady, Supplier Part Number 1=2065596
Logo2: library part Pb-Free
Logo3: library part FCC_disclaimer, "FCC_disclaimer"
NT1 NT2 NT3 NT5 NT7 NT8: "Single point connection between nets."
Q1: library part CMP-0077286-1, "MOSFET, N-CH, 60 V, 75 A, AEC-Q101, PowerPAK_SO-8L", Alternate Manufacturer=None, Manufacturer=Vishay-Siliconix, Supplier Part Number 1=SQJA04EP-T1_GE3CT-ND, Value1="? ohm", Value2="35 nC"
Q2: library part "MMBTA05LT1G, ON Semiconductor", "Transistor, NPN, 60 V, 0.5 A, AEC-Q101, SOT-23", Manufacturer="ON Semiconductor", Supplier Part Number 1=MMBTA05LT1GOSCT-ND, Value1="0.5 A"
Q3 Q4 Q5 Q6 Q7 Q8 Q9 Q10 Q11 Q12 Q13 Q14 Q15: library part CMP-0077287-1, "MOSFET, N-CH, 60 V, 57 A, AEC-Q101, PowerPAK_SO-8L", Alternate Manufacturer=None, Manufacturer=Vishay-Siliconix, Supplier Part Number 1=SQJA06EP-T1_GE3CT-ND, Value1="? ohm", Value2="27 nC"
Q16: "MOSFET, N-CH, 60 V, 0.38 A, AEC-Q101, SOT-23", Alternate Manufacturer=None, Manufacturer="Diodes Inc.", Supplier Part Number 1=DMN62D0U-7DICT-ND, Value1="2 ohm", Value2="0.5 nC"
R1: "RES, 0.001, 1%, 3 W, AEC-Q200 Grade 0, 2512", Manufacturer=Bourns, Power_W=3, Supplier Part Number 1=CRE2512-FZ-R001E-3CT-ND, TempCo="50 ppm/C", Tolerance_%=1, Value1=1%, Value2=3W, Value_Code=1L000, ValueDisplayed=0.001
R2 R3 R20 R30 R36 R40 R44 R54: "RES, 10 k, 5%, 0.063 W, 0402", Manufacturer=Vishay-Dale, Power_W=0.063, Supplier Part Number 1=541-10KJCT-ND, TempCo="200 ppm/C", Tolerance_%=5, Value1=5%, Value2=0.063W, Value_Code=10k0, ValueDisplayed=10k
R4 R6 R8 R10 R12 R13 R14 R16 R17 R19 R22 R25 R27 R35 R41 R42 R43 R52 R53: "RES, 0, 5%, 0.063 W, 0402", Manufacturer=Panasonic, Power_W=0.063, Supplier Part Number 1=P0.0JCT-ND, TempCo="600 ppm/C", Tolerance_%=5, Value1=5%, Value2=0.063W, Value_Code=0000, ValueDisplayed=0
R5: "RES, 2.55 k, 1%, 0.063 W, 0402", Manufacturer=Vishay-Dale, Power_W=0.063, Supplier Part Number 1=541-2.55KLCT-ND, TempCo="100 ppm/C", Tolerance_%=1, Value1=1%, Value2=0.063W, Value_Code=2k55, ValueDisplayed=2.55k
R7: "RES, 43 k, 5%, 0.063 W, 0402", Manufacturer=Vishay-Dale, Power_W=0.063, Supplier Part Number 1=541-43KJCT-ND, TempCo="200 ppm/C", Tolerance_%=5, Value1=5%, Value2=0.063W, Value_Code=43k0, ValueDisplayed=43k
R9: "RES, 200, 5%, 0.1 W, 0603", Manufacturer=Vishay-Dale, Power_W=0.1, Supplier Part Number 1=541-200GCT-ND, TempCo="200 ppm/C", Tolerance_%=5, Value1=5%, Value2=0.1W, Value_Code=200R, ValueDisplayed=200
R11 R15 R21: "RES, 100 k, 5%, 0.063 W, 0402", Manufacturer=Vishay-Dale, Power_W=0.063, Supplier Part Number 1=541-100KJCT-ND, TempCo="200 ppm/C", Tolerance_%=5, Value1=5%, Value2=0.063W, Value_Code=100k
R18: "RES, 0.003, 1%, 3 W, AEC-Q200 Grade 0, 2512", Manufacturer=Bourns, Power_W=3, Supplier Part Number 1=CRE2512-FZ-R003E-3CT-ND, TempCo="50 ppm/C", Tolerance_%=1, Value1=1%, Value2=3W, Value_Code=3L000, ValueDisplayed=0.003
R23 R29 R31 R37 R45 R50: "RES, 68 k, 5%, 0.063 W, 0402", Manufacturer=Vishay-Dale, Power_W=0.063, Supplier Part Number 1=541-68KJCT-ND, TempCo="200 ppm/C", Tolerance_%=5, Value1=5%, Value2=0.063W, Value_Code=68k0, ValueDisplayed=68k
R24 R26 R32 R33 R38 R39 R46 R47 R48 R51: "RES, 200 k, 5%, 0.063 W, 0402", Manufacturer=Vishay-Dale, Power_W=0.063, Supplier Part Number 1=541-200KJCT-ND, TempCo="200 ppm/C", Tolerance_%=5, Value1=5%, Value2=0.063W, Value_Code=200k
R28 R34: "RES, 0.005, 1%, 2 W, 2512", Manufacturer=Ohmite, Power_W=2, Supplier Part Number 1=MCS3264R005FERCT-ND, TempCo="50 ppm/C", Tolerance_%=1, Value1=1%, Value2=2W, Value_Code=5L000, ValueDisplayed=0.005
R49 R55: "RES, 11 k, 5%, 0.063 W, 0402", Manufacturer=Vishay-Dale, Power_W=0.063, Supplier Part Number 1=541-11KJCT-ND, TempCo="200 ppm/C", Tolerance_%=5, Value1=5%, Value2=0.063W, Value_Code=11k0, ValueDisplayed=11k
S1 S2 S3: "Switch, Slide, SP3T, 3 Pos, 0.3 A, 125 VAC, TH", CurrentRating_mA=300, Manufacturer="TE Connectivity", Supplier Part Number 1=450-1570-ND
TP1 TP2 TP3 TP4: library part CMP-0055148-1, "Test Point, Multipurpose, Black, TH", Color=Black, Manufacturer=Keystone, Supplier Part Number 1=36-5011-ND
TP5: library part CMP-0055145-1, "Test Point, Compact, Orange, TH", Color=Orange, Manufacturer=Keystone, Supplier Part Number 1=36-5008-ND
U1: "36-V Low-/High-Side, Overcurrent Protection Comparator, DSQ0010A (WSON-10)", Alternate Manufacturer="Texas Instruments", Alternate PartNumber=INA300AIDSQT
U2: "Automotive, Pin-Selectable Trip Point 1.4V-Capable Family of Temperature Switches, DRL0006A (SOT-OTHER-6)", Alternate Manufacturer="Texas Instruments"
U3: "High Voltage Ultra Low Iq - Low Drop Out Regulator, DBV0005A (SOT-23-5)", Alternate Manufacturer="Texas Instruments"
U4 U6: library part CMP-0076106-1, "Automotive Brushed DC Motor Gate Driver, RHB0032E (VQFN-32)", Alternate Manufacturer="Texas Instruments", Alternate PartNumber=DRV8702DQRHBTQ1
U5 U7: "Automotive Brushed DC Motor Gate Driver, RHB0032E (VQFN-32)", Alternate Manufacturer="Texas Instruments", Alternate PartNumber=DRV8702QRHBTQ1
ZZ1: library part AssemblyNoteLabel, Alternate Manufacturer=-

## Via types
v1: diameter 19.68, hole 7.87, Top Layer to Bottom Layer, 122 vias
v2: diameter 20, hole 8, Top Layer to Bottom Layer, 86 vias

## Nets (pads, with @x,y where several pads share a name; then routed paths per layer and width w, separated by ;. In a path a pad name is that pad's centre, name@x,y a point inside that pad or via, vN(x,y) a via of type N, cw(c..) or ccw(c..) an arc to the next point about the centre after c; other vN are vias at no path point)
3p3V: C1.1 C2.1 C3.1 J4.2 R2.2 R3.2 R4.1 R9.1 R10.1 R11.1 R15.1 R20.1 R21.1 R30.1 R36.1 R44.1 TP5.1 U1.9 U2.5 U3.5 | length 8170.3
  Top Layer w6: R10.1@1240,3443.62 C1.1@1300,3443.62 ; C1.1@1306.38,3450 1314.25,3442.13 U1.9@1314.25,3395.43
  Top Layer w10: TP5.1@260,2660 C3.1@470,2660 510,2700 593.27,2700 U3.5@637.4,2655.87 ; R11.1@630,393.62 v1(630,440) ; R15.1@830,393.62 v1(830,440) ; R21.1@1030,393.62 v1(1030,440) ; v1(1180,3440) R10.1@1236.38,3440 ; R44.1@1203.62,2450 1290,2450 ; R10.1@1240,3443.62 1240,3480 1290,3530 1430,3530 ; 1290,620 v1(1340,620) ; 1290,1600 v1(1340,1600) ; 1290,2610 v1(1330,2610) ; R3.2@1430,3383.62 1430,3530 ; v1(1490,3510) 1470,3530 1430,3530 ; 1620,640 1630,650 R36.1@1656.38,650 ; v1(1690,2610) 1763.62,2683.62 R4.1@1840,2683.62 1869.67,2683.62 1890.22,2663.07 1921.04,2663.07 ; v1(1690,3430) R20.1@1746.38,3430 ; v1(1700,1600) 1766.38,1600 R30.1@1770,1596.38 ; U2.5@1919.09,2688.23 1920.91,2686.42 1920.91,2663.2 1921.04,2663.07 ; C2.1@2000,2636.38 1970.94,2636.38 1944.25,2663.07 1921.04,2663.07
  Top Layer w20: U3.5@637.4,2655.87 699.65,2593.62 R2.2@750,2593.62 806.38,2593.62 830,2570 1290,2570 ; v1(1290,440) 1290,620 1290,1600 1290,2450 1290,2570 ; v1(1290,2820) 1290,2610 1290,2570
  Bottom Layer w10: v1(1180,3440) 1180,2930 v1(1290,2820) ; v1(1330,2610) v1(1690,2610) ; v1(1340,620) 1570,620 1590,640 1620,640 ; v1(1340,1600) v1(1700,1600) ; v1(1490,3510) 1570,3430 v1(1690,3430)
  Bottom Layer w20: J4.2@150,650 360,440 v1(630,440) v1(830,440) v1(1030,440) v1(1290,440)
  other v1: 1610,640
AVDDF: C29.1 R29.1 R45.2 R47.1 U6.14 | length 567.5
  Top Layer w10: R45.2@1880,2966.38 R47.1@1920,2966.38 1926.38,2960 R29.1@1926.38,2860 ; C29.1@1921.5,2910 1941.5,2890 1990,2890 2011.91,2868.09 2011.91,2850 2034.67,2827.24 2147.24,2827.24 2160,2840 2160,2930 2149.53,2940.47 U6.14@2149.53,2965.51
AVDDR: C15.1 R31.1 U5.14 U5.15 | length 822.8
  Top Layer w10: R31.1@1620,1806.38 1620,1630 1720,1530 1970,1530 1990,1550 1990,1591.5 C15.1@1940,1641.5 ; U5.14@1929.53,1745.51 U5.15@1949.21,1745.51 C15.1@1949.21,1650.71
AVDDS: C7.1 R23.2 R24.1 R50.1 U4.14 | length 575.3
  Top Layer w10: R23.2@1900,3576.38 1922.99,3576.38 1931.5,3567.87 C7.1@1931.5,3520 ; R50.1@1926.38,3450 1926.38,3514.88 C7.1@1931.5,3520 ; U4.14@2159.53,3565.51 2159.53,3529.86 2162.24,3527.14 2162.24,3495.84 2174.06,3484.03 2174.06,3434.06 2170,3430 2168.09,3430 2166.51,3428.43 2041.57,3428.43 1970,3500 1951.5,3500 C7.1@1931.5,3520
AVDDW: C23.1 R37.2 U7.14 U7.15 | length 719.8
  Top Layer w10: R37.2@1596.38,800 1580,783.62 1580,630 1670,540 1858.5,540 C23.1@1928.5,610 ; U7.14@1849.53,695.51 U7.15@1869.21,695.51 1869.21,670.79 C23.1@1928.5,611.5
CURRENT_OK: J5.8 R3.1 U1.5 | length 3084.7
  Top Layer w6: J5.8@450,2350 400,2400 400,2470 350,2520 150,2520 100,2570 100,3390 160,3450 1142.45,3450 1241.22,3548.78 1491.22,3548.78 1520,3520 1520,3459.3 1520.72,3458.58 1520.72,3441.42 1520,3440.7 1520,3426.38 R3.1@1430,3336.38 ; U1.5@1361.5,3324.57 1385.43,3324.57 1397.24,3336.38 R3.1@1420,3336.38
DVDDF: C30.1 R52.1 U6.12 | length 126
  Top Layer w10: U6.12@2110.16,2965.51 2110.16,2939.84 2123.62,2926.38 R52.1@2123.62,2910 C30.1@2123.62,2845.12
DVDDR: C16.1 U5.11 U5.12 | length 215.9
  Top Layer w10: C16.1@1880,1578.5 1840,1618.5 1840,1670 1870.47,1700.47 U5.11@1870.47,1745.51 U5.12@1890.16,1745.51
DVDDS: C8.1 R53.1 U4.12 | length 114.4
  Top Layer w10: U4.12@2120.16,3565.51 2120.16,3523.46 R53.1@2133.62,3510 2133.62,3467.87 C8.1@2141.5,3460
DVDDW: C24.1 U7.12 | length 86.4
  Top Layer w10: C24.1@1808.5,610 1810.16,611.65 1810.16,642.09 1810.38,642.32 1810.38,661.11 1810.16,661.34 U7.12@1810.16,695.51
F_SPRAY: J4.6 S3.4 | length 1053.2
  Top Layer w10: J4.6@350,650 400,700 480,700 500,720 500,770 904.45,1174.45 908.78,1174.45 938.23,1203.9 938.23,1208.23 1053.31,1323.31 S3.4@1053.31,1362.52
FAST: J5.4 S1.1 | length 260.5
  Top Layer w10: J5.4@250,2350 250,2150.79 S1.1@293.31,2107.48
FAST_WINDING: J2.1 Q4.1 Q4.2 Q4.3 Q6.5 U6.19 | length 1503.1
  Top Layer w10: U6.19@2214.49,3030.47 2269.53,3030.47 2450,2850 2530,2850 Q6.5@2621.69,2941.69
  Top Layer w100: Q6.5@2691.69,2950 2800,2950 2800,2770 2740,2710 2740,2640 ; 2820,2880 J2.1@3360,2875.2
FASTOK: J5.19 R44.2 U6.10 | length 1375.4
  Top Layer w10: J5.19@1050,2450 R44.2@1156.38,2450 ; v1(2030,2930) 2040.83,2940.83 2060.2,2940.83 2068.9,2949.52 U6.10@2068.9,2963.62
  Bottom Layer w10: J5.19@1050,2450 1170,2570 1720,2570 2030,2880 2029.74,2880.26 v1@2029.74,2929.74
FPARK: J4.14 R12.2 R13.2 | length 314.9
  Top Layer w10: R12.2@670,391.63 710,391.63 710,610 J4.14@750,650
FPARKH: J3.6 R11.2 R12.1 | length 210.5
  Top Layer w10: R11.2@630,346.38 R12.1@670,346.38 680,336.38 J3.6@680,180
FPARKL: J3.5 R13.1 R14.2 | length 218.8
  Top Layer w10: R13.1@710,346.38 R14.2@750,346.38 750,210 J3.5@780,180
FRONT_RTN: J2.3 NT1.2 R18.2 | length 454.4
  Top Layer w10: NT1.2@2910,3750 R18.2@3023.39,3750
  Top Layer w100: R18.2@3050,3699.61 3124.8,3624.8 J2.3@3360,3624.8
GH1R: Q8.4 U5.18 | length 757.1
  Top Layer w10: U5.18@1995.28,1790 2009.44,1790 2190.19,1609.25 2190.75,1609.25 2200,1600 2610,1600 Q8.4@2655,1555
GH1W: Q12.4 U7.18 | length 941.6
  Top Layer w10: U7.18@1916.38,738.9 1931.1,738.9 2210,460 2320,460 2380,520 2660,520 2690.43,489.57 Q12.4@2690.43,475
GH2R: Q9.4 U5.26 | length 995.5
  Top Layer w10: U5.26@1949.21,1934.49 1949.21,1949.21 1980,1980 2070,1980 2303.19,2213.19 2571.1,2213.19 2602.64,2244.73 2602.64,2355.41 2622.87,2375.65 2622.87,2402.87 2625,2405 Q9.4@2660.43,2405
GH2W: Q13.4 U7.26 | length 1049.1
  Top Layer w8: 2019.17,909.17 2126.24,1016.24 2549.9,1016.24
  Top Layer w10: U7.26@1871.1,884.49 1871.1,900.48 1879.8,909.17 2019.17,909.17 ; 2549.9,1016.24 2556.14,1010 2640,1010 2650,1020 2650,1170 Q13.4@2685,1205
GH_FAST: Q4.4 U6.18 | length 578.5
  Top Layer w10: U6.18@2216.06,3012.36 2262.36,3012.36 2444.72,2830 2640,2830 2685,2785 Q4.4@2700.43,2785
GH_SLOW: Q3.4 Q5.4 U4.18 | length 624.4
  Top Layer w10: U4.18@2224.49,3610.79 2226.38,3608.9 2251.1,3608.9 v1(2260,3600) ; v1(2470,3620) 2490,3640 2680,3640 2710,3670 Q3.4@2710,3730 ; 2515,3645 Q5.4@2515,3690.43
  Bottom Layer w10: v1(2260,3600) 2270,3610 2460,3610 v1(2470,3620)
GL1R: Q10.4 U5.20 | length 521.5
  Top Layer w10: U5.20@1994.65,1830 2030,1830 2215,1645 Q10.4@2439.57,1645
GL1W: Q14.4 U7.20 | length 667.6
  Top Layer w10: U7.20@1914.49,780.16 1999.84,780.16 2020,760 2020,720 2140,600 2360,600 2395,565 Q14.4@2469.57,565
GL2R: Q11.4 U5.24 | length 519.3
  Top Layer w10: U5.24@1994.49,1908.9 2025.59,1940 2260,1940 v1(2300.43,1980.43) ; v1(2449.57,1980.43) Q11.4@2449.57,2015
  Bottom Layer w10: v1(2300.43,1980.43) v1(2449.57,1980.43)
GL2W: Q15.4 U7.24 | length 843.9
  Top Layer w8: 2021.1,858.9 2139.08,976.87 2503.13,976.87 2510,970 2510,820
  Top Layer w10: U7.24@1914.49,858.9 2021.1,858.9 ; Q15.4@2469.57,805 2495,805 2510,820
GL_FAST: Q6.4 U6.20 | length 337.6
  Top Layer w10: U6.20@2214.49,3050.16 2275.12,3050.16 2450.28,2875 Q6.4@2479.57,2875
GL_SLOW: Q7.4 U4.20 | length 621.6
  Top Layer w10: U4.20@2224.65,3650 2380,3650 2440,3590 2440,3264.57 Q7.4@2479.57,3225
